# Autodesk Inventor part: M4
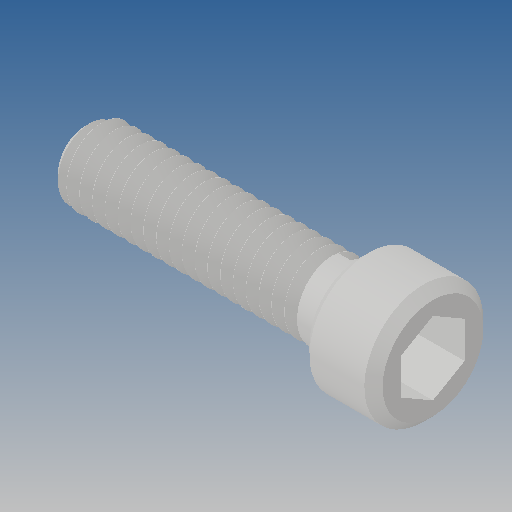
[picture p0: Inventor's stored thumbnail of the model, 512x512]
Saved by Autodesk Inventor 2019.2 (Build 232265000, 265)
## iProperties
Created: 2010-02
Part Number: M4
Material: Ogólny
Document SubType Name: Modeling
Designer: CADENGINEERING4
Density: 1 g/cm^3
Appearance: Domyślna
Author: CADENGINEERING4
Revision Number: 1LAST_VERSION
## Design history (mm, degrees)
feature "Baza1"
node "Bryła1"
